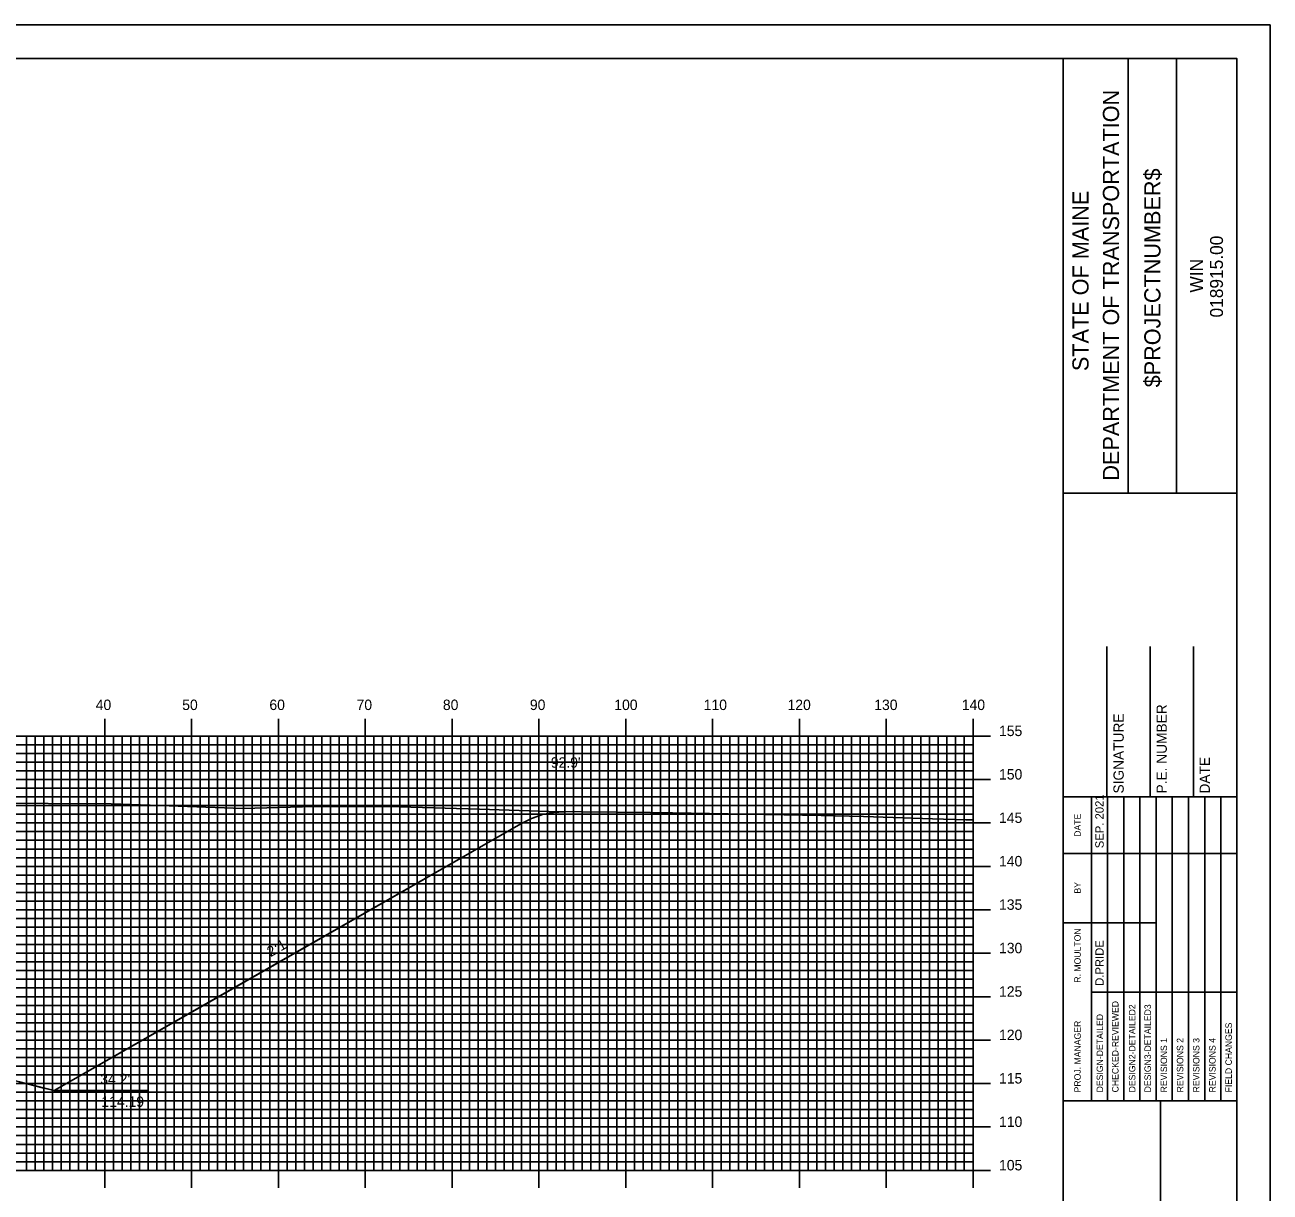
# Model space of a CAD drawing. Extents: x 1769268 to 1769611, y 442591 to 442811.
# Drawn here: x 1769464.3 to 1769607.7, y 442676.2 to 442810.5 of the extents above; entities that cross this region are included whole.
import ezdxf

# ---------------------------------------------------------------- set-up
doc = ezdxf.new("R2010")
doc.units = 0
for name, color, linetype in [('ANNOTATION', 7, 'Continuous'), ('BORDER', 7, 'Continuous'), ('D_Roadway_Centerline', 7, 'Continuous'), ('D_Roadway_SlopeLines', 7, 'Continuous'), ('D_Text_Standard', 7, 'Continuous'), ('H_V ANNOTATION', 7, 'Continuous'), ('MAJOR', 7, 'Continuous'), ('MINOR', 7, 'Continuous'), ('PDRAIN', 7, 'Continuous'), ('PLOT BOUNDARY', 7, 'Continuous'), ('S_Roadway_Centerline', 7, 'Continuous')]:
    doc.layers.add(name, color=color, linetype=linetype)

msp = doc.modelspace()

# ---------------------------------------------------------------- linework, layer by layer
at = {"layer": 'BORDER'}
for p, q in [((1769583.9, 442596.67), (1769583.9, 442806.67)), ((1769591.36, 442756.66), (1769591.36, 442806.66)), ((1769596.95, 442756.66), (1769596.95, 442806.66)), ((1769583.9, 442756.65), (1769603.9, 442756.65)), ((1769588.9, 442721.67), (1769588.9, 442738.97)), ((1769593.9, 442721.67), (1769593.9, 442738.97)), ((1769598.9, 442721.67), (1769598.9, 442738.97)), ((1769583.9, 442721.67), (1769603.9, 442721.67)), ((1769583.9, 442686.67), (1769603.9, 442686.67)), ((1769595.08, 442616.67), (1769595.08, 442686.67))]:
    msp.add_line(p, q, dxfattribs=at)
msp.add_lwpolyline([(1769283.9, 442596.67), (1769603.9, 442596.67), (1769603.9, 442806.67), (1769283.9, 442806.67)], close=True, dxfattribs=at)
for points in [[(1769587.13, 442715.17), (1769587.13, 442721.67)], [(1769589, 442686.68), (1769589, 442721.67)], [(1769590.86, 442721.67), (1769590.86, 442686.68)], [(1769592.72, 442686.68), (1769592.72, 442721.67)], [(1769594.59, 442686.68), (1769594.59, 442721.67)], [(1769596.45, 442686.68), (1769596.45, 442721.67)], [(1769598.31, 442686.68), (1769598.31, 442721.67)], [(1769600.18, 442686.68), (1769600.18, 442721.67)], [(1769602.04, 442686.68), (1769602.04, 442721.67)], [(1769587.13, 442686.68), (1769587.13, 442720.26)], [(1769583.9, 442715.17), (1769603.9, 442715.17)], [(1769583.9, 442707.17), (1769587.13, 442707.17)], [(1769587.13, 442707.17), (1769594.59, 442707.17)], [(1769587.13, 442699.17), (1769603.9, 442699.17)]]:
    msp.add_lwpolyline(points, dxfattribs=at)
at = {"layer": 'D_Roadway_Centerline'}
msp.add_lwpolyline([(1769463.68, 442688.85), (1769466.33, 442688.19), (1769467.68, 442687.85), (1769487.75, 442699.32), (1769521.42, 442718.56), (1769521.42, 442718.56), (1769522.11, 442718.91), (1769522.67, 442719.19), (1769522.9, 442719.27), (1769523.92, 442719.63), (1769524.74, 442719.79), (1769525.17, 442719.88), (1769525.71, 442719.91), (1769526.42, 442719.96)], dxfattribs=at)
at = {"layer": 'D_Roadway_SlopeLines'}
for points in [[(1769467.68, 442687.85), (1769521.42, 442718.56), (1769522.67, 442719.19), (1769523.92, 442719.63), (1769525.17, 442719.88), (1769526.42, 442719.96)], [(1769453.5, 442691.4), (1769467.68, 442687.85)]]:
    msp.add_lwpolyline(points, dxfattribs=at)
at = {"layer": 'MAJOR'}
for p, q in [((1769473.5, 442730.67), (1769473.5, 442728.67)), ((1769483.5, 442730.67), (1769483.5, 442728.67)), ((1769493.5, 442730.67), (1769493.5, 442728.67)), ((1769503.5, 442730.67), (1769503.5, 442728.67)), ((1769513.5, 442730.67), (1769513.5, 442728.67)), ((1769523.5, 442730.67), (1769523.5, 442728.67)), ((1769533.5, 442730.67), (1769533.5, 442728.67)), ((1769543.5, 442730.67), (1769543.5, 442728.67)), ((1769553.5, 442730.67), (1769553.5, 442728.67)), ((1769563.5, 442730.67), (1769563.5, 442728.67)), ((1769573.5, 442730.67), (1769573.5, 442728.67)), ((1769293.5, 442728.67), (1769573.5, 442728.67)), ((1769293.5, 442728.67), (1769573.5, 442728.67)), ((1769473.5, 442678.67), (1769473.5, 442728.67)), ((1769483.5, 442678.67), (1769483.5, 442728.67)), ((1769493.5, 442678.67), (1769493.5, 442728.67)), ((1769503.5, 442678.67), (1769503.5, 442728.67)), ((1769513.5, 442678.67), (1769513.5, 442728.67)), ((1769523.5, 442678.67), (1769523.5, 442728.67)), ((1769533.5, 442678.67), (1769533.5, 442728.67)), ((1769543.5, 442678.67), (1769543.5, 442728.67)), ((1769553.5, 442678.67), (1769553.5, 442728.67)), ((1769563.5, 442678.67), (1769563.5, 442728.67)), ((1769575.51, 442728.67), (1769571.5, 442728.67)), ((1769573.5, 442678.67), (1769573.5, 442728.67)), ((1769573.5, 442678.67), (1769573.5, 442728.67)), ((1769293.5, 442723.67), (1769573.5, 442723.67)), ((1769575.51, 442723.67), (1769571.5, 442723.67)), ((1769293.5, 442718.67), (1769573.5, 442718.67)), ((1769575.51, 442718.67), (1769571.5, 442718.67)), ((1769293.5, 442713.67), (1769573.5, 442713.67)), ((1769575.51, 442713.67), (1769571.5, 442713.67)), ((1769293.5, 442708.67), (1769573.5, 442708.67)), ((1769575.51, 442708.67), (1769571.5, 442708.67)), ((1769293.5, 442703.67), (1769573.5, 442703.67)), ((1769575.51, 442703.67), (1769571.5, 442703.67)), ((1769293.5, 442698.67), (1769573.5, 442698.67)), ((1769575.51, 442698.67), (1769571.5, 442698.67)), ((1769293.5, 442693.67), (1769573.5, 442693.67)), ((1769575.51, 442693.67), (1769571.5, 442693.67)), ((1769293.5, 442688.67), (1769573.5, 442688.67)), ((1769575.51, 442688.67), (1769571.5, 442688.67)), ((1769293.5, 442683.67), (1769573.5, 442683.67)), ((1769575.51, 442683.67), (1769571.5, 442683.67)), ((1769293.5, 442678.67), (1769573.5, 442678.67)), ((1769293.5, 442678.67), (1769573.5, 442678.67)), ((1769473.5, 442676.66), (1769473.5, 442678.67)), ((1769483.5, 442676.66), (1769483.5, 442678.67)), ((1769493.5, 442676.66), (1769493.5, 442678.67)), ((1769503.5, 442676.66), (1769503.5, 442678.67)), ((1769513.5, 442676.66), (1769513.5, 442678.67)), ((1769523.5, 442676.66), (1769523.5, 442678.67)), ((1769533.5, 442676.66), (1769533.5, 442678.67)), ((1769543.5, 442676.66), (1769543.5, 442678.67)), ((1769553.5, 442676.66), (1769553.5, 442678.67)), ((1769563.5, 442676.66), (1769563.5, 442678.67)), ((1769575.51, 442678.67), (1769571.5, 442678.67)), ((1769573.5, 442676.66), (1769573.5, 442678.67))]:
    msp.add_line(p, q, dxfattribs=at)
at = {"layer": 'MINOR'}
for p, q in [((1769464.5, 442678.67), (1769464.5, 442728.67)), ((1769465.5, 442678.67), (1769465.5, 442728.67)), ((1769466.5, 442678.67), (1769466.5, 442728.67)), ((1769467.5, 442678.67), (1769467.5, 442728.67)), ((1769468.5, 442678.67), (1769468.5, 442728.67)), ((1769469.5, 442678.67), (1769469.5, 442728.67)), ((1769470.5, 442678.67), (1769470.5, 442728.67)), ((1769471.5, 442678.67), (1769471.5, 442728.67)), ((1769472.5, 442678.67), (1769472.5, 442728.67)), ((1769474.5, 442678.67), (1769474.5, 442728.67)), ((1769475.5, 442678.67), (1769475.5, 442728.67)), ((1769476.5, 442678.67), (1769476.5, 442728.67)), ((1769477.5, 442678.67), (1769477.5, 442728.67)), ((1769478.5, 442678.67), (1769478.5, 442728.67)), ((1769479.5, 442678.67), (1769479.5, 442728.67)), ((1769480.5, 442678.67), (1769480.5, 442728.67)), ((1769481.5, 442678.67), (1769481.5, 442728.67)), ((1769482.5, 442678.67), (1769482.5, 442728.67)), ((1769484.5, 442678.67), (1769484.5, 442728.67)), ((1769485.5, 442678.67), (1769485.5, 442728.67)), ((1769486.5, 442678.67), (1769486.5, 442728.67)), ((1769487.5, 442678.67), (1769487.5, 442728.67)), ((1769488.5, 442678.67), (1769488.5, 442728.67)), ((1769489.5, 442678.67), (1769489.5, 442728.67)), ((1769490.5, 442678.67), (1769490.5, 442728.67)), ((1769491.5, 442678.67), (1769491.5, 442728.67)), ((1769492.5, 442678.67), (1769492.5, 442728.67)), ((1769494.5, 442678.67), (1769494.5, 442728.67)), ((1769495.5, 442678.67), (1769495.5, 442728.67)), ((1769496.5, 442678.67), (1769496.5, 442728.67)), ((1769497.5, 442678.67), (1769497.5, 442728.67)), ((1769498.5, 442678.67), (1769498.5, 442728.67)), ((1769499.5, 442678.67), (1769499.5, 442728.67)), ((1769500.5, 442678.67), (1769500.5, 442728.67)), ((1769501.5, 442678.67), (1769501.5, 442728.67)), ((1769502.5, 442678.67), (1769502.5, 442728.67)), ((1769504.5, 442678.67), (1769504.5, 442728.67)), ((1769505.5, 442678.67), (1769505.5, 442728.67)), ((1769506.5, 442678.67), (1769506.5, 442728.67)), ((1769507.5, 442678.67), (1769507.5, 442728.67)), ((1769508.5, 442678.67), (1769508.5, 442728.67)), ((1769509.5, 442678.67), (1769509.5, 442728.67)), ((1769510.5, 442678.67), (1769510.5, 442728.67)), ((1769511.5, 442678.67), (1769511.5, 442728.67)), ((1769512.5, 442678.67), (1769512.5, 442728.67)), ((1769514.5, 442678.67), (1769514.5, 442728.67)), ((1769515.5, 442678.67), (1769515.5, 442728.67)), ((1769516.5, 442678.67), (1769516.5, 442728.67)), ((1769517.5, 442678.67), (1769517.5, 442728.67)), ((1769518.5, 442678.67), (1769518.5, 442728.67)), ((1769519.5, 442678.67), (1769519.5, 442728.67)), ((1769520.5, 442678.67), (1769520.5, 442728.67)), ((1769521.5, 442678.67), (1769521.5, 442728.67)), ((1769522.5, 442678.67), (1769522.5, 442728.67)), ((1769524.5, 442678.67), (1769524.5, 442728.67)), ((1769525.5, 442678.67), (1769525.5, 442728.67)), ((1769526.5, 442678.67), (1769526.5, 442728.67)), ((1769527.5, 442678.67), (1769527.5, 442728.67)), ((1769528.5, 442678.67), (1769528.5, 442728.67)), ((1769529.5, 442678.67), (1769529.5, 442728.67)), ((1769530.5, 442678.67), (1769530.5, 442728.67)), ((1769531.5, 442678.67), (1769531.5, 442728.67)), ((1769532.5, 442678.67), (1769532.5, 442728.67)), ((1769534.5, 442678.67), (1769534.5, 442728.67)), ((1769535.5, 442678.67), (1769535.5, 442728.67)), ((1769536.5, 442678.67), (1769536.5, 442728.67)), ((1769537.5, 442678.67), (1769537.5, 442728.67)), ((1769538.5, 442678.67), (1769538.5, 442728.67)), ((1769539.5, 442678.67), (1769539.5, 442728.67)), ((1769540.5, 442678.67), (1769540.5, 442728.67)), ((1769541.5, 442678.67), (1769541.5, 442728.67)), ((1769542.5, 442678.67), (1769542.5, 442728.67)), ((1769544.5, 442678.67), (1769544.5, 442728.67)), ((1769545.5, 442678.67), (1769545.5, 442728.67)), ((1769546.5, 442678.67), (1769546.5, 442728.67)), ((1769547.5, 442678.67), (1769547.5, 442728.67)), ((1769548.5, 442678.67), (1769548.5, 442728.67)), ((1769549.5, 442678.67), (1769549.5, 442728.67)), ((1769550.5, 442678.67), (1769550.5, 442728.67)), ((1769551.5, 442678.67), (1769551.5, 442728.67)), ((1769552.5, 442678.67), (1769552.5, 442728.67)), ((1769554.5, 442678.67), (1769554.5, 442728.67)), ((1769555.5, 442678.67), (1769555.5, 442728.67)), ((1769556.5, 442678.67), (1769556.5, 442728.67)), ((1769557.5, 442678.67), (1769557.5, 442728.67)), ((1769558.5, 442678.67), (1769558.5, 442728.67)), ((1769559.5, 442678.67), (1769559.5, 442728.67)), ((1769560.5, 442678.67), (1769560.5, 442728.67)), ((1769561.5, 442678.67), (1769561.5, 442728.67)), ((1769562.5, 442678.67), (1769562.5, 442728.67)), ((1769564.5, 442678.67), (1769564.5, 442728.67)), ((1769565.5, 442678.67), (1769565.5, 442728.67)), ((1769566.5, 442678.67), (1769566.5, 442728.67)), ((1769567.5, 442678.67), (1769567.5, 442728.67)), ((1769568.5, 442678.67), (1769568.5, 442728.67)), ((1769569.5, 442678.67), (1769569.5, 442728.67)), ((1769570.5, 442678.67), (1769570.5, 442728.67)), ((1769571.5, 442678.67), (1769571.5, 442728.67)), ((1769572.5, 442678.67), (1769572.5, 442728.67)), ((1769293.5, 442727.67), (1769573.5, 442727.67)), ((1769573.5, 442727.67), (1769571.5, 442727.67)), ((1769293.5, 442726.67), (1769573.5, 442726.67)), ((1769293.5, 442725.67), (1769573.5, 442725.67)), ((1769573.5, 442726.67), (1769571.5, 442726.67)), ((1769573.5, 442725.67), (1769571.5, 442725.67)), ((1769293.5, 442724.67), (1769573.5, 442724.67)), ((1769573.5, 442724.67), (1769571.5, 442724.67)), ((1769293.5, 442722.67), (1769573.5, 442722.67)), ((1769573.5, 442722.67), (1769571.5, 442722.67)), ((1769293.5, 442721.67), (1769573.5, 442721.67)), ((1769573.5, 442721.67), (1769571.5, 442721.67)), ((1769293.5, 442720.67), (1769573.5, 442720.67)), ((1769293.5, 442719.67), (1769573.5, 442719.67)), ((1769573.5, 442720.67), (1769571.5, 442720.67)), ((1769573.5, 442719.67), (1769571.5, 442719.67)), ((1769293.5, 442717.67), (1769573.5, 442717.67)), ((1769573.5, 442717.67), (1769571.5, 442717.67)), ((1769293.5, 442716.67), (1769573.5, 442716.67)), ((1769293.5, 442715.67), (1769573.5, 442715.67)), ((1769573.5, 442716.67), (1769571.5, 442716.67)), ((1769573.5, 442715.67), (1769571.5, 442715.67)), ((1769293.5, 442714.67), (1769573.5, 442714.67)), ((1769573.5, 442714.67), (1769571.5, 442714.67)), ((1769293.5, 442712.67), (1769573.5, 442712.67)), ((1769573.5, 442712.67), (1769571.5, 442712.67)), ((1769293.5, 442711.67), (1769573.5, 442711.67)), ((1769573.5, 442711.67), (1769571.5, 442711.67)), ((1769293.5, 442710.67), (1769573.5, 442710.67)), ((1769293.5, 442709.67), (1769573.5, 442709.67)), ((1769573.5, 442710.67), (1769571.5, 442710.67)), ((1769573.5, 442709.67), (1769571.5, 442709.67)), ((1769293.5, 442707.67), (1769573.5, 442707.67)), ((1769573.5, 442707.67), (1769571.5, 442707.67)), ((1769293.5, 442706.67), (1769573.5, 442706.67)), ((1769293.5, 442705.67), (1769573.5, 442705.67)), ((1769573.5, 442706.67), (1769571.5, 442706.67)), ((1769573.5, 442705.67), (1769571.5, 442705.67)), ((1769293.5, 442704.67), (1769573.5, 442704.67)), ((1769573.5, 442704.67), (1769571.5, 442704.67)), ((1769293.5, 442702.67), (1769573.5, 442702.67)), ((1769573.5, 442702.67), (1769571.5, 442702.67)), ((1769293.5, 442701.67), (1769573.5, 442701.67)), ((1769573.5, 442701.67), (1769571.5, 442701.67)), ((1769293.5, 442700.67), (1769573.5, 442700.67)), ((1769293.5, 442699.67), (1769573.5, 442699.67)), ((1769573.5, 442700.67), (1769571.5, 442700.67)), ((1769573.5, 442699.67), (1769571.5, 442699.67)), ((1769293.5, 442697.67), (1769573.5, 442697.67)), ((1769573.5, 442697.67), (1769571.5, 442697.67)), ((1769293.5, 442696.67), (1769573.5, 442696.67)), ((1769293.5, 442695.67), (1769573.5, 442695.67)), ((1769573.5, 442696.67), (1769571.5, 442696.67)), ((1769573.5, 442695.67), (1769571.5, 442695.67)), ((1769293.5, 442694.67), (1769573.5, 442694.67)), ((1769573.5, 442694.67), (1769571.5, 442694.67)), ((1769293.5, 442692.67), (1769573.5, 442692.67)), ((1769573.5, 442692.67), (1769571.5, 442692.67)), ((1769293.5, 442691.67), (1769573.5, 442691.67)), ((1769573.5, 442691.67), (1769571.5, 442691.67)), ((1769293.5, 442690.67), (1769573.5, 442690.67)), ((1769293.5, 442689.67), (1769573.5, 442689.67)), ((1769573.5, 442690.67), (1769571.5, 442690.67)), ((1769573.5, 442689.67), (1769571.5, 442689.67)), ((1769293.5, 442687.67), (1769573.5, 442687.67)), ((1769573.5, 442687.67), (1769571.5, 442687.67)), ((1769293.5, 442686.67), (1769573.5, 442686.67)), ((1769293.5, 442685.67), (1769573.5, 442685.67)), ((1769573.5, 442686.67), (1769571.5, 442686.67)), ((1769573.5, 442685.67), (1769571.5, 442685.67)), ((1769293.5, 442684.67), (1769573.5, 442684.67)), ((1769573.5, 442684.67), (1769571.5, 442684.67)), ((1769293.5, 442682.67), (1769573.5, 442682.67)), ((1769573.5, 442682.67), (1769571.5, 442682.67)), ((1769293.5, 442681.67), (1769573.5, 442681.67)), ((1769573.5, 442681.67), (1769571.5, 442681.67)), ((1769293.5, 442680.67), (1769573.5, 442680.67)), ((1769293.5, 442679.67), (1769573.5, 442679.67)), ((1769573.5, 442680.67), (1769571.5, 442680.67)), ((1769573.5, 442679.67), (1769571.5, 442679.67))]:
    msp.add_line(p, q, dxfattribs=at)
at = {"layer": 'PDRAIN'}
msp.add_line((1769467.68, 442687.85), (1769478.45, 442687.85), dxfattribs=at)
at = {"layer": 'PLOT BOUNDARY'}
msp.add_lwpolyline([(1769267.72, 442590.55), (1769607.72, 442590.55), (1769607.72, 442810.55), (1769267.72, 442810.55)], close=True, dxfattribs=at)
at = {"layer": 'S_Roadway_Centerline'}
msp.add_lwpolyline([(1769459.72, 442720.96), (1769474.26, 442720.88), (1769479.85, 442720.68), (1769489.42, 442720.35), (1769497.68, 442720.55), (1769507.46, 442720.52), (1769516.65, 442720.25), (1769524.64, 442719.97), (1769536.34, 442719.89), (1769538.91, 442719.85), (1769556.03, 442719.52), (1769560.89, 442719.4), (1769568.82, 442719.16), (1769572.67, 442719.04), (1769573.5, 442719.03)], dxfattribs=at)

# ---------------------------------------------------------------- texts
at = {"layer": 'ANNOTATION'}
msp.add_text('2:1', height=1.2, rotation=29.7445, dxfattribs=at).set_placement((1769492.62, 442703.21))
for s, p in [("34.2'", (1769472.99, 442688.58)), ('114.19', (1769473.12, 442685.98))]:
    msp.add_text(s, height=1.2, dxfattribs=at).set_placement(p)
at = {"layer": 'BORDER'}
for s, height, p in [('DEPARTMENT OF TRANSPORTATION', 1.8635, (1769590.32, 442758.08)), ('$PROJECTNUMBER$', 1.8635, (1769595.09, 442768.82)), ('STATE OF MAINE', 1.8635, (1769586.81, 442770.69)), ('018915.00', 1.491, (1769602.29, 442776.86)), ('WIN', 1.491, (1769599.98, 442779.73)), ('SIGNATURE', 1.181, (1769590.86, 442722.06)), ('P.E. NUMBER', 1.1811, (1769595.82, 442722.06)), ('DATE', 1.181, (1769600.78, 442722.06)), ('SEP. 2021', 0.969, (1769588.55, 442715.76)), ('DATE', 0.743, (1769585.91, 442717.08)), ('BY', 0.743, (1769585.91, 442710.54)), ('R. MOULTON', 0.745, (1769585.91, 442700.28)), ('D.PRIDE', 0.969, (1769588.55, 442699.92)), ('CHECKED-REVIEWED', 0.7455, (1769590.26, 442687.65)), ('DESIGN2-DETAILED2', 0.7455, (1769592.2, 442687.65)), ('DESIGN3-DETAILED3', 0.7455, (1769593.99, 442687.65)), ('PROJ. MANAGER', 0.7455, (1769585.91, 442687.65)), ('DESIGN-DETAILED', 0.7455, (1769588.48, 442687.65)), ('FIELD CHANGES', 0.7455, (1769603.31, 442687.65)), ('REVISIONS 1', 0.7455, (1769595.85, 442687.65)), ('REVISIONS 2', 0.7455, (1769597.72, 442687.65)), ('REVISIONS 3', 0.7455, (1769599.58, 442687.65)), ('REVISIONS 4', 0.7455, (1769601.44, 442687.65))]:
    msp.add_text(s, height=height, rotation=90, dxfattribs=at).set_placement(p)
at = {"layer": 'D_Text_Standard'}
msp.add_text("92.9'", height=1.2, dxfattribs=at).set_placement((1769524.88, 442725.03))
at = {"layer": 'H_V ANNOTATION'}
for s, p in [('40', (1769472.47, 442731.67)), ('50', (1769482.43, 442731.67)), ('60', (1769492.47, 442731.67)), ('70', (1769502.51, 442731.67)), ('80', (1769512.45, 442731.67)), ('90', (1769522.47, 442731.67)), ('100', (1769532.19, 442731.67)), ('110', (1769542.49, 442731.67)), ('120', (1769552.14, 442731.67)), ('130', (1769562.13, 442731.67)), ('140', (1769572.21, 442731.67)), ('155', (1769576.5, 442728.67)), ('150', (1769576.5, 442723.67)), ('145', (1769576.5, 442718.67)), ('140', (1769576.5, 442713.67)), ('135', (1769576.5, 442708.67)), ('130', (1769576.5, 442703.67)), ('125', (1769576.5, 442698.67)), ('120', (1769576.5, 442693.67)), ('115', (1769576.5, 442688.67)), ('110', (1769576.5, 442683.67)), ('105', (1769576.5, 442678.67))]:
    msp.add_text(s, height=1.2, dxfattribs=at).set_placement(p)

doc.saveas('drawing.dxf')
